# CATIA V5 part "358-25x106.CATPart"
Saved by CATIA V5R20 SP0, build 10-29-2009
Part number: 358-25X106
Definition: NONE
Nomenclature: 358-25X106
Source: Unknown
Description: 358-25X106
Bounding box of the stored display mesh (mm): x -17 to 89, y -19 to 19, z -19 to 19
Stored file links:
  C:\Users\Utente\Desktop\IO LAVORO\3D X SITO CF\X SITO\PLASTICA\358\358-25x106.CATPart
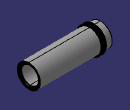
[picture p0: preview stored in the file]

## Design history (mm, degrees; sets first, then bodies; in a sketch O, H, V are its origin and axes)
Body1 "358-25X106" (main body)
  Solid1: solid without history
